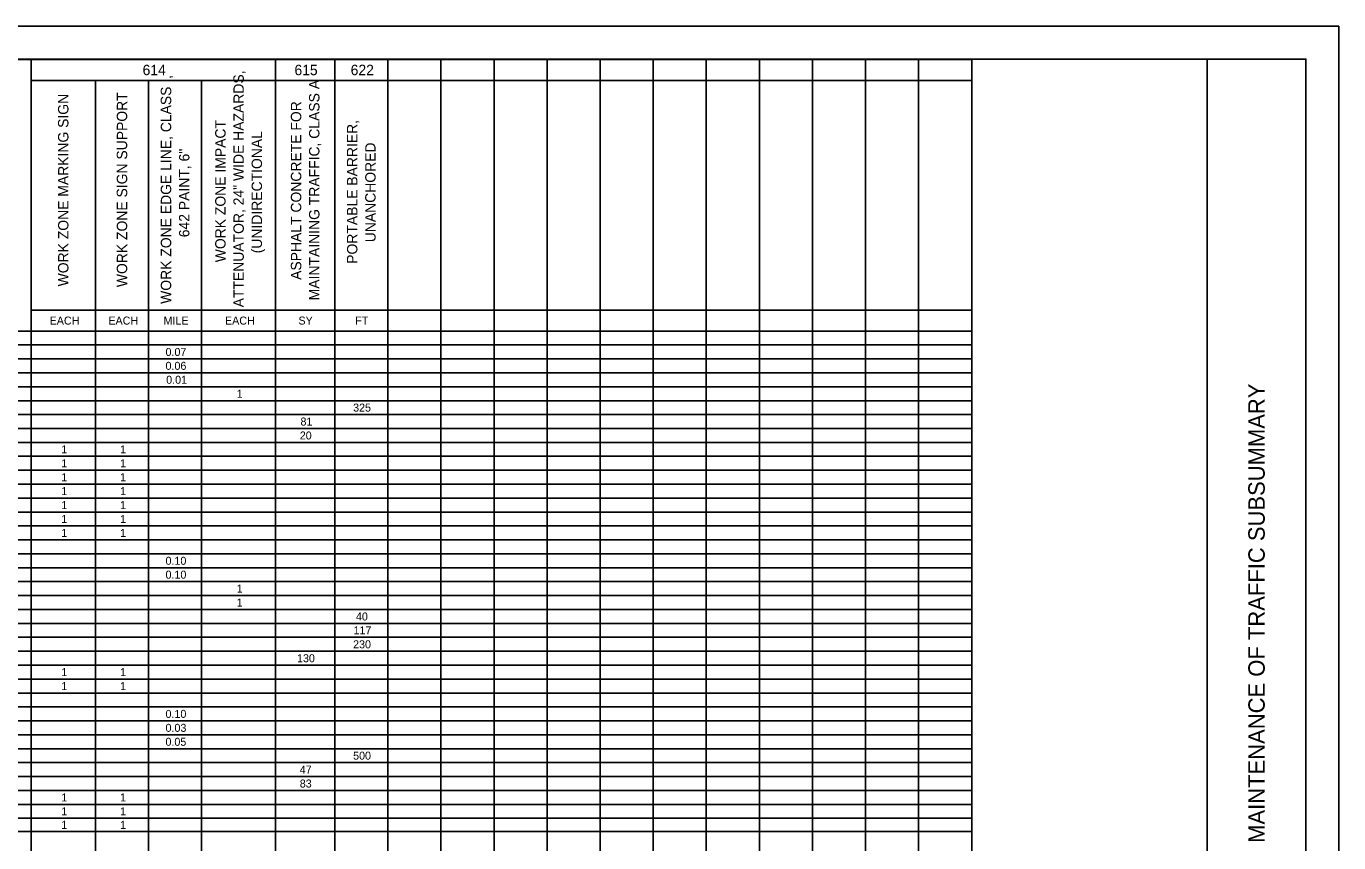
# Model space of a CAD drawing. Extents: x 0 to 35.8, y 0 to 22.
# Drawn here: x 14.05 to 34, y 9.59 to 22 of the extents above; entities that cross this region are included whole.
import ezdxf

# ---------------------------------------------------------------- set-up
doc = ezdxf.new("R2010")
doc.units = 0
for name, color, linetype in [('SH_Border', 7, 'Continuous'), ('SH_Cut_Line', 7, 'Continuous'), ('SH_Data', 7, 'Continuous'), ('SH_Text', 7, 'Continuous')]:
    doc.layers.add(name, color=color, linetype=linetype)

msp = doc.modelspace()

# ---------------------------------------------------------------- linework, layer by layer
at = {"layer": 'SH_Border'}
msp.add_line((32, 0.5), (32, 21.5), dxfattribs=at)
msp.add_lwpolyline([(1.5, 21.5), (33.5, 21.5), (33.5, 0.5), (1.5, 0.5)], close=True, dxfattribs=at)
at = {"layer": 'SH_Cut_Line'}
msp.add_lwpolyline([(0, 0), (34, 0), (34, 22), (0, 22)], close=True, dxfattribs=at)
at = {"layer": 'SH_Text'}
for p, q in [((7.212, 21.494), (28.42, 21.494)), ((14.118, 21.494), (14.118, 3.302)), ((17.836, 21.494), (17.836, 3.302)), ((18.736, 21.494), (18.736, 3.302)), ((19.543, 21.494), (19.543, 3.302)), ((20.35, 21.494), (20.35, 3.302)), ((21.157, 21.494), (21.157, 3.302)), ((21.964, 21.494), (21.964, 3.302)), ((22.771, 21.494), (22.771, 3.302)), ((23.578, 21.494), (23.578, 3.302)), ((24.385, 21.494), (24.385, 3.302)), ((25.192, 21.494), (25.192, 3.302)), ((25.999, 21.494), (25.999, 3.302)), ((26.806, 21.494), (26.806, 3.302)), ((27.613, 21.494), (27.613, 3.302)), ((28.42, 21.494), (28.42, 3.302)), ((14.118, 21.176), (28.42, 21.176)), ((15.097, 21.176), (15.097, 3.302)), ((15.904, 21.176), (15.904, 3.302)), ((16.711, 21.176), (16.711, 3.302)), ((14.118, 17.683), (28.42, 17.683)), ((7.212, 17.366), (28.42, 17.366)), ((7.212, 17.154), (28.42, 17.154)), ((7.212, 16.942), (28.42, 16.942)), ((7.212, 16.731), (28.42, 16.731)), ((7.212, 16.519), (28.42, 16.519)), ((7.212, 16.307), (28.42, 16.307)), ((7.212, 16.096), (28.42, 16.096)), ((7.212, 15.884), (28.42, 15.884)), ((7.212, 15.672), (28.42, 15.672)), ((7.212, 15.461), (28.42, 15.461)), ((7.212, 15.249), (28.42, 15.249)), ((7.212, 15.037), (28.42, 15.037)), ((7.212, 14.826), (28.42, 14.826)), ((7.212, 14.614), (28.42, 14.614)), ((7.212, 14.402), (28.42, 14.402)), ((7.212, 14.191), (28.42, 14.191)), ((7.212, 13.979), (28.42, 13.979)), ((7.212, 13.767), (28.42, 13.767)), ((7.212, 13.556), (28.42, 13.556)), ((7.212, 13.344), (28.42, 13.344)), ((7.212, 13.132), (28.42, 13.132)), ((7.212, 12.92), (28.42, 12.92)), ((7.212, 12.709), (28.42, 12.709)), ((7.212, 12.497), (28.42, 12.497)), ((7.212, 12.285), (28.42, 12.285)), ((7.212, 12.074), (28.42, 12.074)), ((7.212, 11.862), (28.42, 11.862)), ((7.212, 11.65), (28.42, 11.65)), ((7.212, 11.439), (28.42, 11.439)), ((7.212, 11.227), (28.42, 11.227)), ((7.212, 11.015), (28.42, 11.015)), ((7.212, 10.804), (28.42, 10.804)), ((7.212, 10.592), (28.42, 10.592)), ((7.212, 10.38), (28.42, 10.38)), ((7.212, 10.169), (28.42, 10.169)), ((7.212, 9.957), (28.42, 9.957)), ((7.212, 9.759), (28.42, 9.759))]:
    msp.add_line(p, q, dxfattribs=at)

# ---------------------------------------------------------------- texts
at = {"layer": 'SH_Data'}
msp.add_text('MAINTENANCE OF TRAFFIC SUBSUMMARY', height=0.25, rotation=90, dxfattribs=at).set_placement((32.875, 9.584))
at = {"layer": 'SH_Text'}
for s, height, p in [('614', 0.1582, (15.814, 21.256)), ('615', 0.1582, (18.123, 21.256)), ('622', 0.1582, (18.978, 21.256)), ('EACH', 0.1217, (14.401, 17.464)), ('EACH', 0.1217, (15.294, 17.464)), ('MILE', 0.1217, (16.133, 17.464)), ('EACH', 0.1217, (17.067, 17.464)), ('SY', 0.1217, (18.184, 17.464)), ('FT', 0.1217, (19.047, 17.464)), ('0.07', 0.1217, (16.163, 16.987)), ('0.06', 0.1217, (16.163, 16.776)), ('0.01', 0.1217, (16.173, 16.564)), ('1', 0.122, (17.245, 16.352)), ('325', 0.1217, (19.015, 16.141)), ('81', 0.1217, (18.215, 15.929)), ('20', 0.1217, (18.204, 15.717)), ('1', 0.122, (14.579, 15.506)), ('1', 0.122, (15.472, 15.506)), ('1', 0.122, (14.579, 15.294)), ('1', 0.122, (15.472, 15.294)), ('1', 0.122, (14.579, 15.082)), ('1', 0.122, (15.472, 15.082)), ('1', 0.122, (14.579, 14.871)), ('1', 0.122, (15.472, 14.871)), ('1', 0.122, (14.579, 14.659)), ('1', 0.122, (15.472, 14.659)), ('1', 0.122, (14.579, 14.447)), ('1', 0.122, (15.472, 14.447)), ('1', 0.122, (14.579, 14.236)), ('1', 0.122, (15.472, 14.236)), ('0.10', 0.1217, (16.163, 13.812)), ('0.10', 0.1217, (16.163, 13.601)), ('1', 0.122, (17.245, 13.389)), ('1', 0.122, (17.245, 13.177)), ('40', 0.1217, (19.058, 12.965)), ('117', 0.1217, (19.021, 12.754)), ('230', 0.1217, (19.015, 12.542)), ('130', 0.1217, (18.162, 12.33)), ('1', 0.122, (14.579, 12.119)), ('1', 0.122, (15.472, 12.119)), ('1', 0.122, (14.579, 11.907)), ('1', 0.122, (15.472, 11.907)), ('0.10', 0.1217, (16.163, 11.484)), ('0.03', 0.1217, (16.163, 11.272)), ('0.05', 0.1217, (16.162, 11.06)), ('500', 0.1217, (19.015, 10.849)), ('47', 0.1217, (18.204, 10.637)), ('83', 0.1217, (18.204, 10.425)), ('1', 0.122, (14.579, 10.214)), ('1', 0.122, (15.472, 10.214)), ('1', 0.122, (14.579, 10.002)), ('1', 0.122, (15.472, 10.002)), ('1', 0.122, (14.579, 9.797)), ('1', 0.122, (15.472, 9.797))]:
    msp.add_text(s, height=height, dxfattribs=at).set_placement(p)
for s, height, p in [('WORK ZONE EDGE LINE, CLASS I, ', 0.15823, (16.249, 17.779)), ('ATTENUATOR, 24" WIDE HAZARDS, ', 0.15823, (17.353, 17.726)), ('MAINTAINING TRAFFIC, CLASS A', 0.15823, (18.503, 17.833)), ('WORK ZONE MARKING SIGN', 0.15823, (14.687, 18.045)), ('WORK ZONE SIGN SUPPORT', 0.15823, (15.58, 18.033)), ('ASPHALT CONCRETE FOR ', 0.15823, (18.227, 18.144)), ('WORK ZONE IMPACT ', 0.15823, (17.076, 18.411)), ('PORTABLE BARRIER, ', 0.15823, (19.08, 18.388)), ('(UNIDIRECTIONAL', 0.15823, (17.63, 18.548)), ('UNANCHORED', 0.1582, (19.357, 18.716)), ('642 PAINT, 6"', 0.15823, (16.526, 18.792))]:
    msp.add_text(s, height=height, rotation=90, dxfattribs=at).set_placement(p)

doc.saveas('drawing.dxf')
